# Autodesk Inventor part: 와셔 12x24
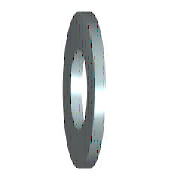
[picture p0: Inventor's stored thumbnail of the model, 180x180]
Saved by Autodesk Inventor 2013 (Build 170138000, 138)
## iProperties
IsCustomPart: 1
Created: 2012-02
Part Number: 와셔 12x24
Material: 스테인리스강
Description: 평면 와셔
Document SubType Name: Modeling
Standard: KS B 1326
Designer: mduedu
Standards Organization: KS
Language: ko-KR
Size Designation: 12x24
Categories: <MemberInstance><Categories><Category DisplayName="조임쇠" InternalName="e4da775c-781d-43d5-af7c-5136215cf5a6" Mnemonic="FSTN"><Category DisplayName="와셔" InternalN
Density: 1 g/cm^3
Author: mduedu
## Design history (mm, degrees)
sketch "스케치"
  geometry: C1 r 12 at (0, 0); C2 r 6.5 at (0, 0); 1 further point
  constraints: 2 centre point, 2 coincident
  dimensions: "d0" = 13 diameter of C2 (= SD1); "d1" = 24 diameter of C1 (= SD2)
extrude "본체" new body sketch "스케치" distance "d2" = 2.5 (= SD); taper "d3" = 0 deg
workaxis "Work Axis1"
workplane "Work Plane1"
body "Solid1"
other parameters: "SD1" = 13 [user parameter; used in 1 equation term], "SD2" = 24 [user parameter; used in 1 equation term], "SD" = 2.5 [user parameter; used in 1 equation term], "d4" = 0, "d5" = 0, "d6" = 0, "d7" = 0, "NND" = 12 [user parameter]
